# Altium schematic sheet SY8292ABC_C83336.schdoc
size 127 x 101 mm
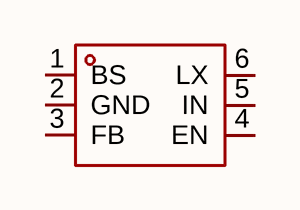
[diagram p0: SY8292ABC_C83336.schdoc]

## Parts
U?  sy8292abc_c83336  [SOT-23-6_L2.9-W1.6-P0.95-LS2.8-BR]  (value not drawn)

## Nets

Not connected (* = marked no-connect by the designer): U? 1(BS) 2(GND) 3(FB) 4(EN) 5(IN) 6(LX)

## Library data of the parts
U? = sy8292abc_c83336: 功能类型:降压型;工作电压:5V~40V;输出电压:-;输出电流:2A;输出类型:可调;; Manufacturer: Silergy(矽力杰); AddInBom: yes; ModelId: 18da8f6c14a34920b3e136b5c401a119; ModelName: SOT-23-6_L2.9-W1.6-H1.5-LS2.8-P0.95; ModelTransform: 110.73671,114.173,0,180,0,0,0.001,-0.003,0; Function: 降压型; Voltage - Supply: 5V~40V; Output Current: 2A; Frequency - Switching: 800kHz; Synchronous Rectifier: 否; Number of Outputs: 1; Topology: 降压式; Quiescent Current: 160uA; Switch tube (built-in/external): 内置; Output Type: 可调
